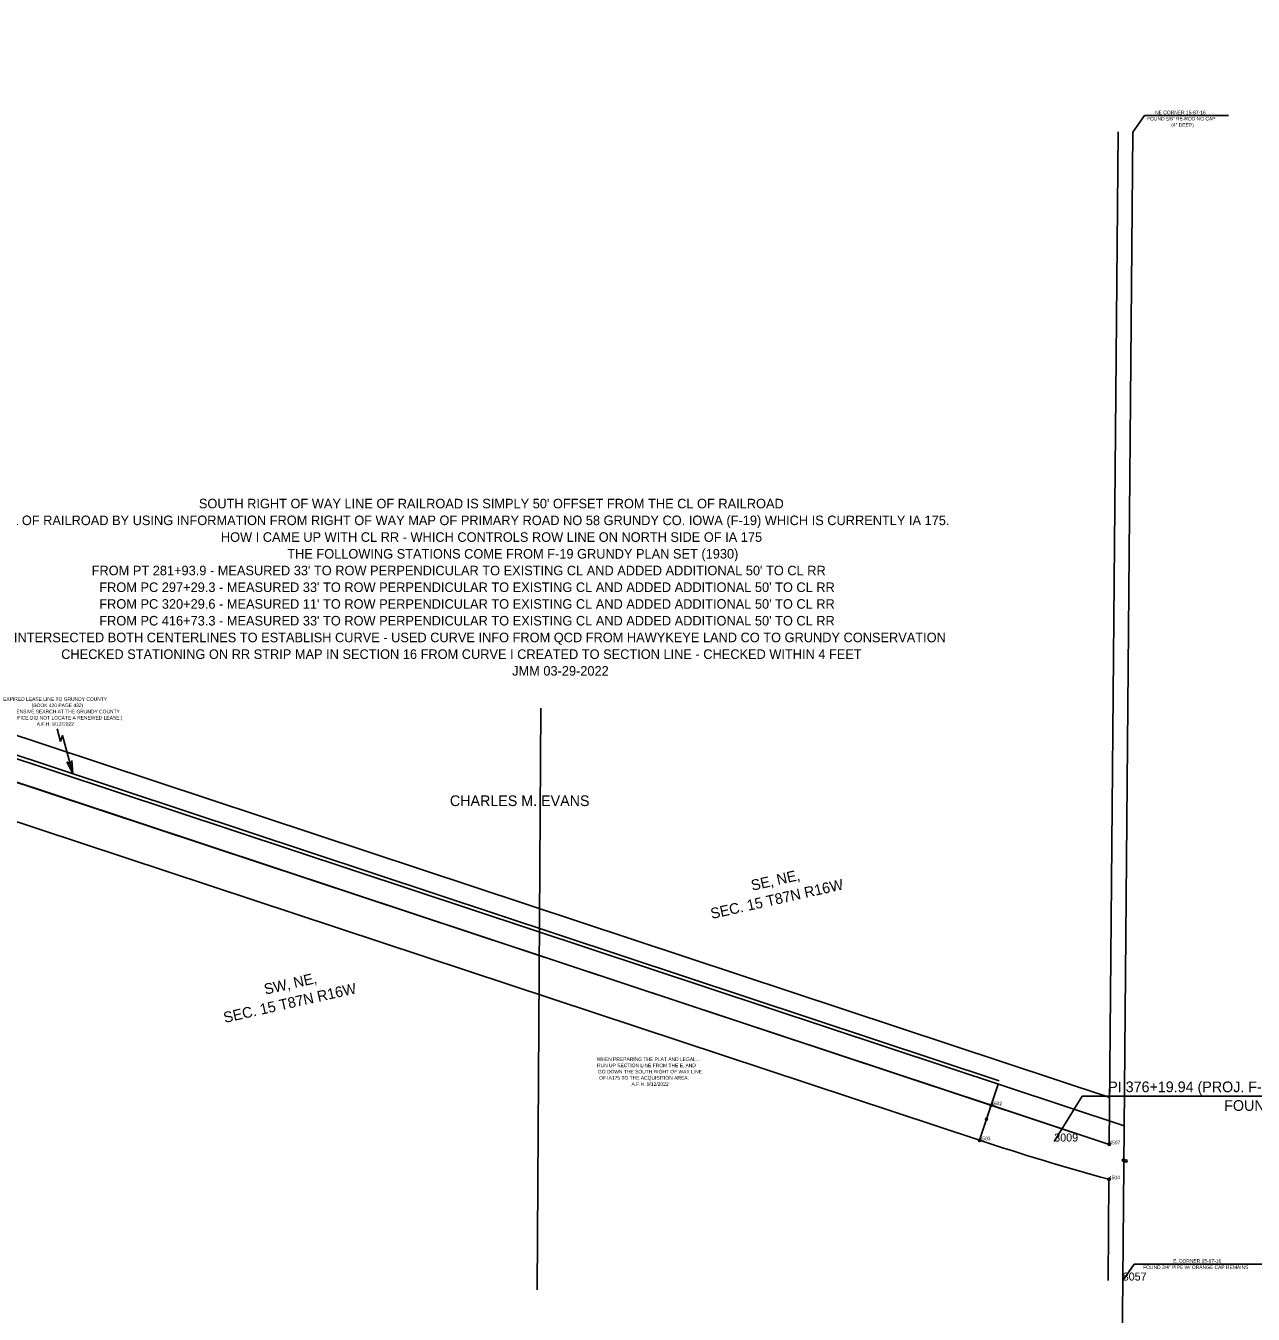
# Model space of a CAD drawing. Extents: x 15369911 to 15383386, y 8787425 to 8795569.
# Drawn here: x 15378514 to 15381274, y 8789990 to 8792887 of the extents above; entities that cross this region are included whole.
import ezdxf

# ---------------------------------------------------------------- set-up
doc = ezdxf.new("R2010")
doc.units = 0
for name, color, linetype in [('Default', 7, 'Continuous'), ('DisCLMLSURPoints', 7, 'Continuous'), ('DisCLMLSURText', 7, 'Continuous'), ('DisCLSRORText', 7, 'Continuous'), ('DisCLSRSURPoints', 7, 'Continuous'), ('DisCLSRSURText', 7, 'Continuous'), ('DisFence', 7, 'Continuous'), ('DisFieldPoint', 7, 'Continuous'), ('DisFieldPointName', 7, 'Continuous'), ('DisFills', 7, 'Continuous'), ('DisMisc1', 7, 'Continuous')]:
    doc.layers.add(name, color=color, linetype=linetype)

msp = doc.modelspace()

# ---------------------------------------------------------------- linework, layer by layer
at = {"layer": 'Default'}
for p, q in [((15373646.3, 8792792.4), (15380950.2, 8790372)), ((15378369.4, 8791288.3), (15380702.8, 8790515.1)), ((15378592.1, 8791277.8), (15378584.3, 8791306.2)), ((15378606.5, 8791232.3), (15378606.4, 8791232.3)), ((15378606.5, 8791232.3), (15378606.5, 8791232.3)), ((15378620, 8791205.2), (15378606.5, 8791232.3)), ((15378617.9, 8791235.3), (15378617.9, 8791235.3)), ((15378617.9, 8791235.3), (15378617.9, 8791235.3)), ((15378617.9, 8791235.3), (15378617.9, 8791235.3)), ((15378617.9, 8791235.3), (15378620, 8791205.2)), ((15378617.9, 8791235.3), (15378617.9, 8791235.3))]:
    msp.add_line(p, q, dxfattribs=at)
msp.add_lwpolyline([(15378620, 8791205.2), (15378596.4, 8791291), (15378592.1, 8791277.8)], dxfattribs=at)
msp.add_arc((15378611.8, 8791235.2), 6.1, 208.7215, 1.0904, dxfattribs=at)
at = {"layer": 'DisCLMLSURPoints'}
for centre in [(15380684.5, 8790460), (15380684.5, 8790460), (15380684.5, 8790460), (15380674.2, 8790428.7), (15380658.5, 8790381.2), (15380950.2, 8790372), (15380981.4, 8790336.5), (15380982.9, 8790336.1), (15380988, 8790334.7), (15380949.5, 8790293.4)]:
    msp.add_circle(centre, 2.5, dxfattribs=at)
at = {"layer": 'DisCLMLSURText'}
for p, q in [((15380950.2, 8790372), (15380970.2, 8792648.6)), ((15380684.5, 8790460), (15378351.1, 8791233.3)), ((15380658.5, 8790381.2), (15378350.7, 8791144.6)), ((15380950.2, 8790372), (15380684.5, 8790460)), ((15380947.5, 8790066), (15380949.5, 8790293.4))]:
    msp.add_line(p, q, dxfattribs=at)
msp.add_arc((15382473.6, 8795868.9), 5780.1, 251.69714, 254.71082, dxfattribs=at)
at = {"layer": 'DisCLSRORText'}
for p, q in [((15381003.2, 8792648.3), (15381029.2, 8792685.3)), ((15381029.2, 8792685.3), (15381218.2, 8792685.3)), ((15380980.5, 8790065.7), (15381003.2, 8792648.3)), ((15379664.1, 8790044.6), (15379672.3, 8791352.5)), ((15380980.5, 8790065.7), (15381006.5, 8790102.8)), ((15381006.5, 8790102.8), (15381325.3, 8790102.8)), ((15380980.5, 8790065.7), (15380958.9, 8787425))]:
    msp.add_line(p, q, dxfattribs=at)
at = {"layer": 'DisFence'}
for p, q in [((15380951.1, 8790477), (15373677.7, 8792887.3)), ((15380983.6, 8790413.6), (15373662, 8792839.8)), ((15380674.2, 8790428.7), (15380700.2, 8790507.5)), ((15380658.5, 8790381.2), (15380674.2, 8790428.7))]:
    msp.add_line(p, q, dxfattribs=at)
at = {"layer": 'DisFieldPointName'}
for p, q in [((15380826.5, 8790378.3), (15380889.3, 8790480.3)), ((15380889.3, 8790480.3), (15381899.4, 8790480.3))]:
    msp.add_line(p, q, dxfattribs=at)
at = {"layer": 'DisMisc1'}
msp.add_line((15378351.1, 8791233.3), (15380684.5, 8790460), dxfattribs=at)

# ---------------------------------------------------------------- texts
at = {"layer": 'Default'}
for s, p in [('EXPIRED LEASE LINE TO GRUNDY COUNTY', (15378463, 8791369.2)), ('(AFTER AN EXTENSIVE SEARCH AT THE GRUNDY COUNTY ', (15378410, 8791341.2)), ('(BOOK 420 PAGE 432)', (15378527.1, 8791355.2)), ("RECORDER'S OFFICE DID NOT LOCATE A RENEWED LEASE.)", (15378404, 8791327.2)), ('A.F.H. 9/12/2022', (15378538.6, 8791313.2))]:
    msp.add_text(s, height=8, dxfattribs=at).set_placement(p)
at = {"layer": 'DisCLMLSURText'}
for s, p in [('4502', (15380684.5, 8790460)), ('4503', (15380658.5, 8790381.2)), ('4507', (15380950.2, 8790372)), ('4504', (15380949.5, 8790293.4))]:
    msp.add_text(s, height=8, dxfattribs=at).set_placement(p)
at = {"layer": 'DisCLSRORText'}
for s, p in [('FOUND 5/8" RE-ROD NO CAP', (15381035.4, 8792674.3)), ('NE CORNER 15-87-16', (15381053.3, 8792688.3)), ('(4" DEEP)', (15381089.6, 8792660.3)), ('FOUND 3/4" PIPE W/ ORANGE CAP REMAINS', (15381026.4, 8790091.8)), ('E‚ CORNER 15-87-16', (15381093.9, 8790105.8))]:
    msp.add_text(s, height=8, dxfattribs=at).set_placement(p)
for s, p in [('SEC. 15 T87N R16W', (15380056.6, 8790878.6)), ('SE‚ NE‚', (15380147.7, 8790942.2)), ('SEC. 15 T87N R16W', (15378961.5, 8790644.9)), ('SW‚ NE‚', (15379052.7, 8790708.5))]:
    msp.add_text(s, height=24, rotation=12.6865, dxfattribs=at).set_placement(p)
at = {"layer": 'DisCLSRSURPoints'}
for s, height, p in [("SOUTH RIGHT OF WAY LINE OF RAILROAD IS SIMPLY 50' OFFSET FROM THE CL OF RAILROAD", 21.495, (15378903.2, 8791802.1)), ('COMPUTED CL OF RAILROAD BY USING INFORMATION FROM RIGHT OF WAY MAP OF PRIMARY ROAD NO 58 GRUNDY CO. IOWA (F-19) WHICH IS CURRENTLY IA 175.', 21.495, (15378288, 8791764.4)), ('HOW I CAME UP WITH CL RR - WHICH CONTROLS ROW LINE ON NORTH SIDE OF IA 175 ', 21.495, (15378952.7, 8791726.8)), ('THE FOLLOWING STATIONS COME FROM F-19 GRUNDY PLAN SET (1930) ', 21.495, (15379102, 8791689.2)), (" FROM PT 281+93.9 - MEASURED 33' TO ROW PERPENDICULAR TO EXISTING CL AND ADDED ADDITIONAL 50' TO CL RR ", 21.495, (15378654.1, 8791651.6)), ("FROM PC 297+29.3 - MEASURED 33' TO ROW PERPENDICULAR TO EXISTING CL AND ADDED ADDITIONAL 50' TO CL RR", 21.495, (15378679.3, 8791614)), ("FROM PC 320+29.6 - MEASURED 11' TO ROW PERPENDICULAR TO EXISTING CL AND ADDED ADDITIONAL 50' TO CL RR", 21.495, (15378679.3, 8791576.4)), ("FROM PC 416+73.3 - MEASURED 33' TO ROW PERPENDICULAR TO EXISTING CL AND ADDED ADDITIONAL 50' TO CL RR", 21.495, (15378679.3, 8791538.7)), ('INTERSECTED BOTH CENTERLINES TO ESTABLISH CURVE - USED CURVE INFO FROM QCD FROM HAWYKEYE LAND CO TO GRUNDY CONSERVATION', 21.495, (15378487.4, 8791501.1)), ('CHECKED STATIONING ON RR STRIP MAP IN SECTION 16 FROM CURVE I CREATED TO SECTION LINE - CHECKED WITHIN 4 FEET', 21.495, (15378593.6, 8791463.5)), ('JMM 03-29-2022', 21.495, (15379607.5, 8791425.9)), ('WHEN PREPARING THE PLAT AND LEGAL...', 8, (15379797.7, 8790559.5)), ('RUN UP SECTION LINE FROM THE E‚ AND', 8, (15379798.4, 8790545.5)), ('GO DOWN THE SOUTH RIGHT OF WAY LINE', 8, (15379800.5, 8790531.5)), ('OF IA175 TO THE ACQUISITION AREA. ', 8, (15379803, 8790517.5)), ('A.F.H. 9/12/2022', 8, (15379876, 8790503.5))]:
    msp.add_text(s, height=height, dxfattribs=at).set_placement(p)
at = {"layer": 'DisCLSRSURText'}
msp.add_text('CHARLES M. EVANS', height=24, dxfattribs=at).set_placement((15379467.6, 8791132.7))
at = {"layer": 'DisFieldPoint'}
msp.add_text('8057', height=18, dxfattribs=at).set_placement((15380980.5, 8790065.7))
at = {"layer": 'DisFieldPointName'}
for s, p in [('PI 376+19.94 (PROJ. F-175-9(6)--20-38)', (15380947.9, 8790489.3)), ('FOUND HINGE NAIL', (15381208.7, 8790447.3))]:
    msp.add_text(s, height=24, dxfattribs=at).set_placement(p)
at = {"layer": 'DisFills'}
msp.add_text('3009', height=18, dxfattribs=at).set_placement((15380826.5, 8790378.3))

doc.saveas('drawing.dxf')
